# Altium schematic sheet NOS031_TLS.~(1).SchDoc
size A4
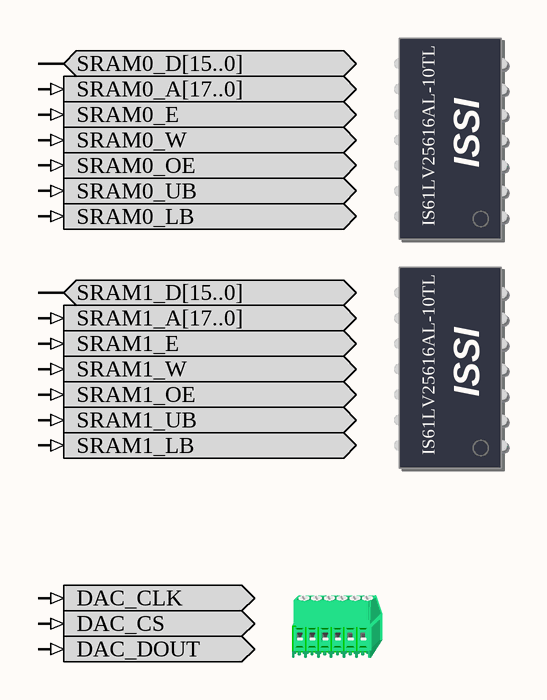
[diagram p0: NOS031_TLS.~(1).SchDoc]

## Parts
(Parts that share a designator on the sheet are numbered #1, #2 ... from top to bottom, then left to right.)
?#1  SRAM0  (value not drawn)
?#2  SRAM1  (value not drawn)
?#3  ADCDAC  (value not drawn)

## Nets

Not connected (* = marked no-connect by the designer): ?#1 SRAM0_A[17..0] SRAM0_D[15..0] SRAM0_E SRAM0_LB SRAM0_OE SRAM0_UB SRAM0_W; ?#2 SRAM1_A[17..0] SRAM1_D[15..0] SRAM1_E SRAM1_LB SRAM1_OE SRAM1_UB SRAM1_W; ?#3 DAC_CLK DAC_CS DAC_DOUT

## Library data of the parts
?#1 = SRAM0: Free Static RAM - Daughterboard; PortComponent: True
?#2 = SRAM1: Free Static RAM - Daughterboard; PortComponent: True
?#3 = DAC: Digital Analog Converter; PortComponent: True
